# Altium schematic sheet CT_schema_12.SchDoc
size 281 x 153 mm
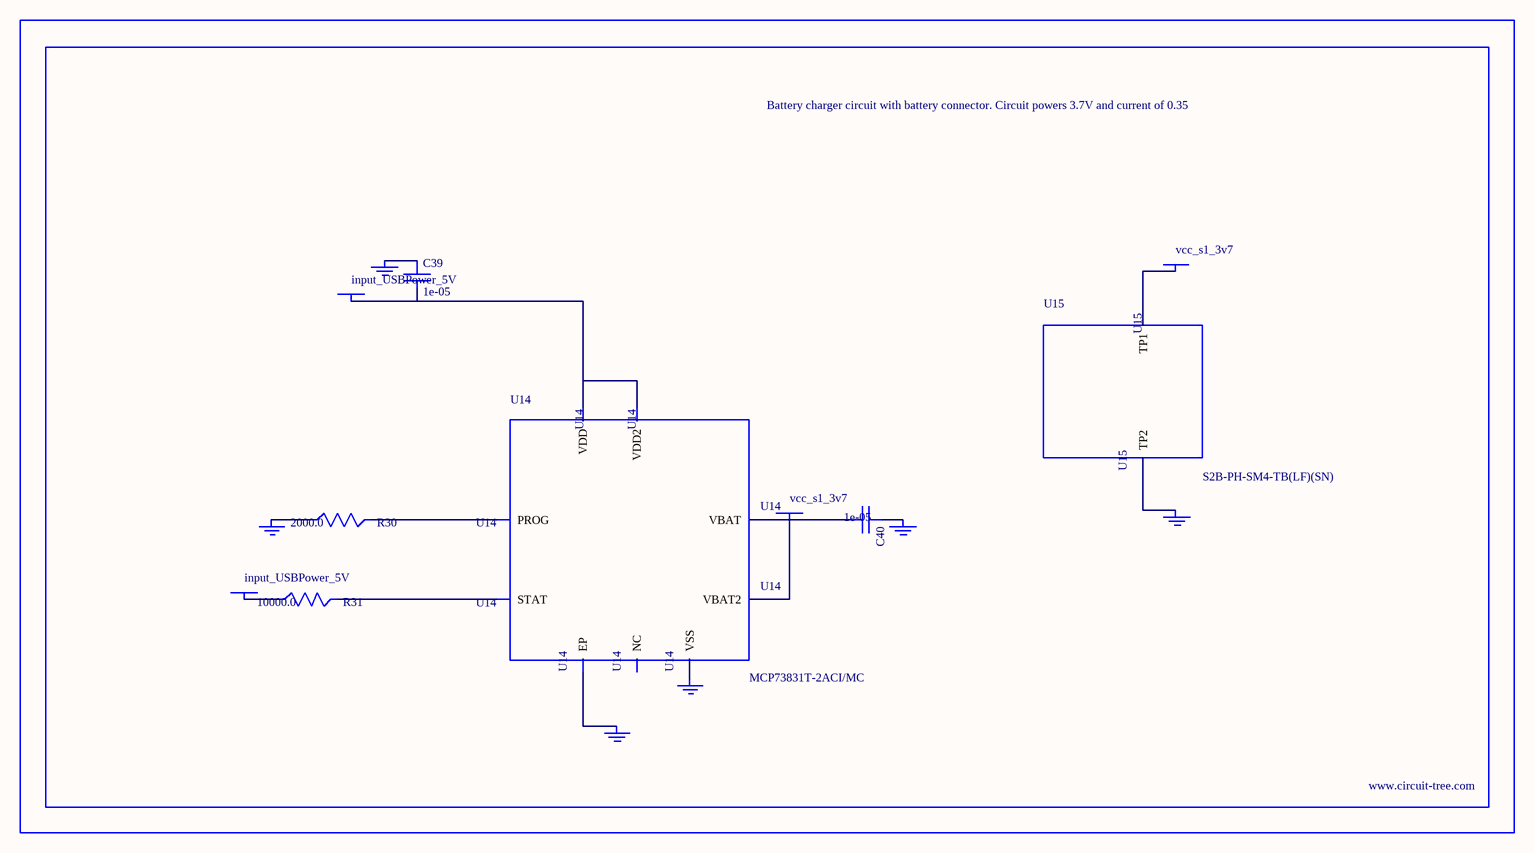
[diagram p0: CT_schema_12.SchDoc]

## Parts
BORDER11  (no value)
C39  1e-05  [C1206]
C40  1e-05  [C1206]
GND_INSTANCE_11_0  (no value)
GND_INSTANCE_11_1  (no value)
GND_INSTANCE_11_2  (no value)
GND_INSTANCE_11_3  (no value)
GND_INSTANCE_11_4  (no value)
GND_INSTANCE_11_5  (no value)
POWER_INSTANCE_11_0  input_USBPower_5V
POWER_INSTANCE_11_1  input_USBPower_5V
POWER_INSTANCE_11_2  vcc_s1_3v7
POWER_INSTANCE_11_3  vcc_s1_3v7
R30  2000.0  [R0603]
R31  10000.0  [R0603]
U14  MCP73831T-2ACI/MC  [DFN8_2X3MC]
U15  S2B-PH-SM4-TB(LF)(SN)  [JST-2-SMD]

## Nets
NetC39_1: C39.1 GND_INSTANCE_11_0.0(GND)
NetC39_2: C39.2 POWER_INSTANCE_11_0.0(PWR) U14.1(VDD) U14.2(VDD2)
NetC40_1: C40.1 GND_INSTANCE_11_1.0(GND)
NetC40_2: C40.2 POWER_INSTANCE_11_2.0(PWR) U14.3(VBAT) U14.4(VBAT2)
NetGND_INSTANCE_11_2_0: GND_INSTANCE_11_2.0(GND) R30.1
NetGND_INSTANCE_11_3_0: GND_INSTANCE_11_3.0(GND) U14.9(EP)
NetGND_INSTANCE_11_4_0: GND_INSTANCE_11_4.0(GND) U14.6(VSS)
NetGND_INSTANCE_11_5_0: GND_INSTANCE_11_5.0(GND) U15.2(TP2)
NetPOWER_INSTANCE_11_1_0: POWER_INSTANCE_11_1.0(PWR) R31.1
NetPOWER_INSTANCE_11_3_0: POWER_INSTANCE_11_3.0(PWR) U15.1(TP1)
NetR30_2: R30.2 U14.8(PROG)
NetR31_2: R31.2 U14.5(STAT)

Not connected (* = marked no-connect by the designer): U14 7(NC)

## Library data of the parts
BORDER11 = BORDER_PAGE11
C39 C40 = C1206C106K3RACTU
GND_INSTANCE_11_0-GND_INSTANCE_11_5 = GND
POWER_INSTANCE_11_0-POWER_INSTANCE_11_3 = PWR
R30 = RC0603JR-072KL
R31 = RC0603JR-0710KL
